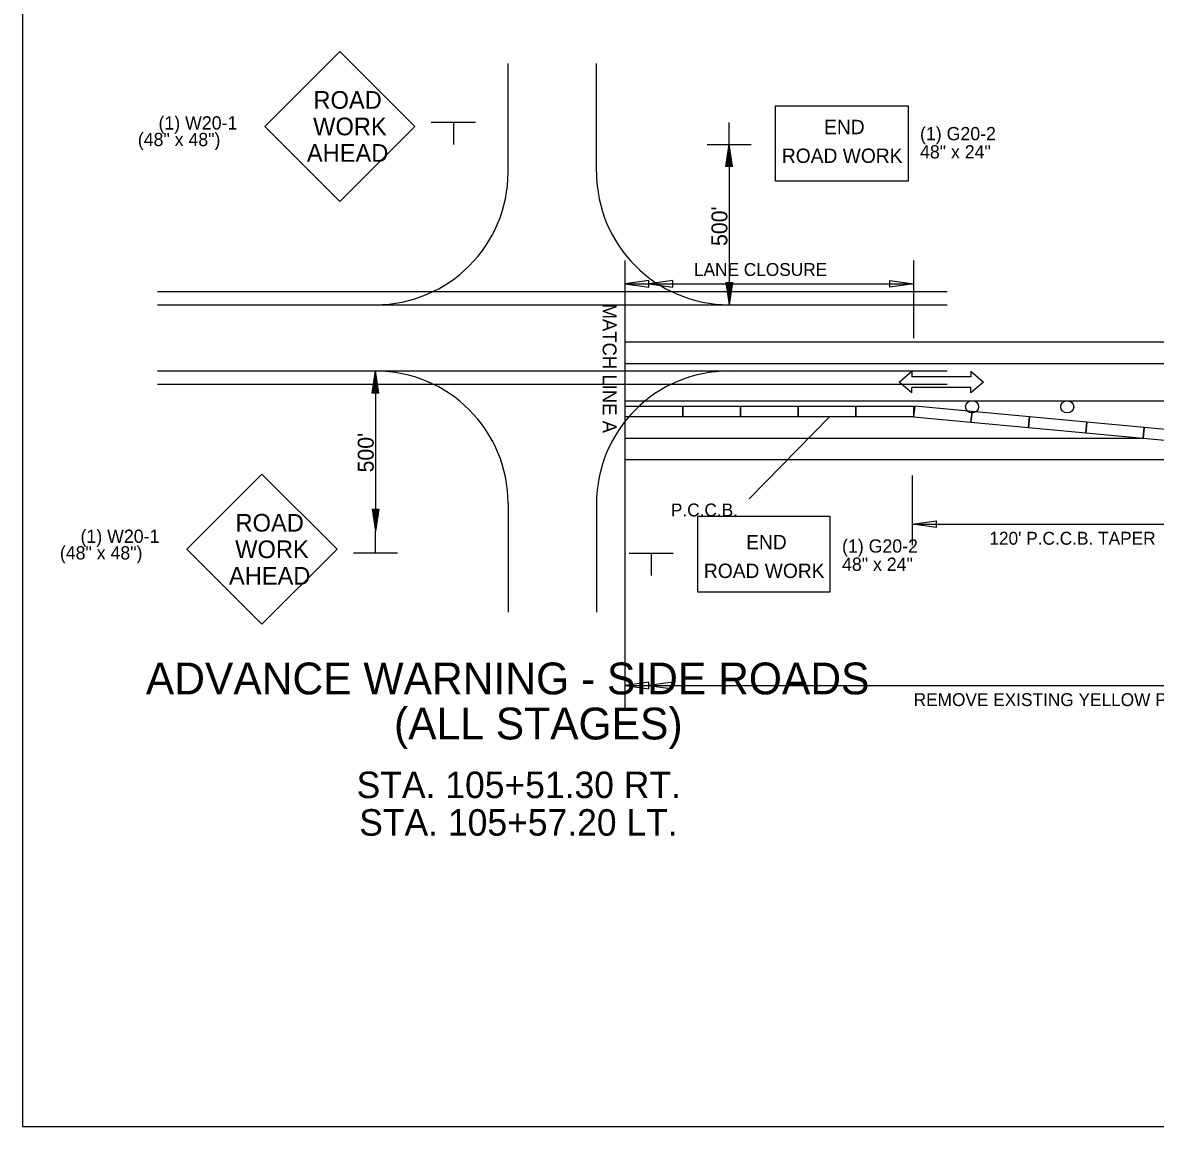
# Model space of a CAD drawing. Extents: x 1807779 to 1818251, y 673292 to 678849.
# Drawn here: x 1810701 to 1811213, y 676380 to 676879 of the extents above; entities that cross this region are included whole.
import ezdxf

# ---------------------------------------------------------------- set-up
doc = ezdxf.new("R2010")
doc.units = 0
for name, color, linetype in [('_ALL STAGES SIGNS', 7, 'Continuous'), ('Default', 7, 'Continuous'), ('DSN_DRFT_Guideline-No-Plot', 7, 'Continuous'), ('R_Draft', 7, 'Continuous'), ('R_MOT', 7, 'Continuous'), ('S_PHOTO_CTL_ANNOT', 7, 'Continuous'), ('T_Vehicle Path Rt', 7, 'Continuous')]:
    doc.layers.add(name, color=color, linetype=linetype)

# ---------------------------------------------------------------- blocks, each defined once
blk = doc.blocks.new('ARROW')
at = {"layer": 'R_Draft'}
for p, q in [((-0.2, 0.03), (0, 0)), ((-0.2, 0.03), (-0.2, -0.03)), ((-0.2, 0.025), (-0.0334, 0)), ((-0.2, 0.0199), (-0.0678, 0)), ((-0.2, 0.0149), (-0.1011, 0)), ((-0.2, 0.0097), (-0.135, 0)), ((-0.2, 0.0047), (-0.1684, 0)), ((-0.2, -0.03), (0, 0)), ((-0.2, -0.0098), (-0.135, 0)), ((-0.2, -0.0199), (-0.0678, 0)), ((-0.2, -0.025), (-0.0334, 0)), ((-0.2, -0.0149), (-0.1011, 0)), ((-0.2, -0.0047), (-0.1684, 0))]:
    blk.add_line(p, q, dxfattribs=at)

msp = doc.modelspace()

# ---------------------------------------------------------------- linework, layer by layer
at = {"layer": '_ALL STAGES SIGNS'}
for points in [[(1810844.4, 676866.37), (1810810.46, 676832.43), (1810844.4, 676798.49), (1810878.34, 676832.43)], [(1810809.13, 676607.12), (1810775.19, 676641.06), (1810809.13, 676675), (1810843.07, 676641.06)]]:
    msp.add_lwpolyline(points, close=True, dxfattribs=at)
at = {"layer": 'Default'}
for p, q in [((1810905.74, 676834.23), (1810885.74, 676834.23)), ((1810895.74, 676834.23), (1810895.74, 676824.23)), ((1811020.47, 676824.23), (1811020.47, 676834.23)), ((1811010.47, 676824.23), (1811030.47, 676824.23)), ((1811020.47, 676824.23), (1811020.47, 676751.75)), ((1810973.46, 676568.94), (1810973.46, 676771.74)), ((1811103.92, 676771.74), (1811103.92, 676736.57)), ((1810984.21, 676762.76), (1810973.46, 676761.25)), ((1810984.21, 676759.75), (1810984.21, 676762.76)), ((1810994.96, 676762.76), (1810984.21, 676761.25)), ((1810994.96, 676759.75), (1810994.96, 676762.76)), ((1811093.17, 676759.75), (1811093.17, 676762.76)), ((1811093.17, 676762.76), (1811103.92, 676761.25)), ((1810973.46, 676761.25), (1811103.92, 676761.25)), ((1810973.46, 676761.25), (1810984.21, 676759.75)), ((1810984.21, 676761.25), (1810994.96, 676759.75)), ((1811103.92, 676761.25), (1811093.17, 676759.75)), ((1810973.46, 676734.92), (1811130.01, 676734.92)), ((1811130.01, 676734.92), (1812078.25, 676734.92)), ((1810860.47, 676721.75), (1810860.47, 676649.26)), ((1810973.46, 676725.19), (1811130.01, 676725.19)), ((1811130.01, 676725.19), (1811412.11, 676725.19)), ((1810973.46, 676708.29), (1811517.44, 676708.29)), ((1811029.52, 676663.93), (1811065.87, 676700.99)), ((1810973.46, 676691.38), (1811130.01, 676691.38)), ((1811130.01, 676691.38), (1811207.5, 676691.38)), ((1810973.46, 676681.65), (1811130.01, 676681.65)), ((1811130.01, 676681.65), (1812078.25, 676681.65)), ((1811103.4, 676642.96), (1811103.4, 676674.42)), ((1811103.4, 676652.48), (1811114.15, 676653.98)), ((1811103.4, 676652.48), (1811259.55, 676652.48)), ((1811114.15, 676650.98), (1811103.4, 676652.48)), ((1811114.15, 676653.98), (1811114.15, 676650.98)), ((1810860.47, 676639.26), (1810860.47, 676649.26)), ((1810870.47, 676639.26), (1810850.47, 676639.26)), ((1810975.19, 676639.26), (1810995.19, 676639.26)), ((1810985.19, 676639.26), (1810985.19, 676629.26)), ((1810984.21, 676580.94), (1810973.46, 676579.43)), ((1810973.46, 676579.43), (1811519.69, 676579.43)), ((1810973.46, 676579.43), (1810984.21, 676577.93)), ((1810984.21, 676577.93), (1810984.21, 676580.94)), ((1810994.96, 676580.94), (1810984.21, 676579.43)), ((1810984.21, 676579.43), (1810994.96, 676577.93)), ((1810994.96, 676577.93), (1810994.96, 676580.94))]:
    msp.add_line(p, q, dxfattribs=at)
for points in [[(1811101.46, 676841.71), (1811101.46, 676807.63), (1811041.47, 676807.63), (1811041.47, 676841.71)], [(1811066.19, 676621.79), (1811066.19, 676655.87), (1811006.2, 676655.87), (1811006.2, 676621.79)]]:
    msp.add_lwpolyline(points, close=True, dxfattribs=at)
msp.add_lwpolyline([(1810973.46, 676708.29), (1811259.55, 676708.29)], dxfattribs=at)
for centre in [(1811130.4, 676705.55), (1811173.45, 676705.55)]:
    msp.add_ellipse(centre, major_axis=(-2.94, 0), ratio=0.93178, dxfattribs=at)
at = {"layer": 'DSN_DRFT_Guideline-No-Plot'}
msp.add_lwpolyline([(1810700.85, 676379.88), (1812350.85, 676379.88), (1812350.85, 677378.94), (1810700.85, 677378.94)], close=True, dxfattribs=at)
at = {"layer": 'R_MOT'}
for p, q in [((1811097.48, 676716.74), (1811103.21, 676721.6)), ((1811103.21, 676721.6), (1811103.21, 676719.17)), ((1811129.8, 676721.6), (1811135.52, 676716.74)), ((1811129.8, 676721.6), (1811129.8, 676719.17)), ((1811103.21, 676711.88), (1811097.48, 676716.74)), ((1811129.8, 676719.17), (1811103.21, 676719.17)), ((1811135.52, 676716.74), (1811129.8, 676711.88)), ((1811129.8, 676714.31), (1811103.21, 676714.31)), ((1811103.21, 676711.88), (1811103.21, 676714.31)), ((1811129.8, 676711.88), (1811129.8, 676714.31))]:
    msp.add_line(p, q, dxfattribs=at)
at = {"layer": 'S_PHOTO_CTL_ANNOT'}
for p, q in [((1810920.47, 676811.75), (1810920.47, 676860.85)), ((1810960.47, 676811.75), (1810960.47, 676860.85)), ((1810761.85, 676757.75), (1811119.08, 676757.75)), ((1810761.85, 676751.75), (1811119.08, 676751.75)), ((1810761.85, 676721.75), (1811119.08, 676721.75)), ((1810761.85, 676715.75), (1811119.08, 676715.75)), ((1810920.47, 676661.75), (1810920.47, 676612.64)), ((1810960.47, 676661.75), (1810960.47, 676612.64))]:
    msp.add_line(p, q, dxfattribs=at)
for centre, start, end in [((1810860.47, 676811.75), 270, 0), ((1811020.47, 676811.75), 180, 270), ((1810860.47, 676661.75), 360, 90), ((1811020.47, 676661.75), 90, 180)]:
    msp.add_arc(centre, 60, start, end, dxfattribs=at)
at = {"layer": 'T_Vehicle Path Rt'}
for points in [[(1810973.46, 676705.85), (1810999.55, 676705.85), (1810999.55, 676700.99), (1810973.46, 676700.99)], [(1810999.55, 676705.85), (1811025.64, 676705.85), (1811025.64, 676700.99), (1810999.55, 676700.99)], [(1811025.64, 676705.85), (1811051.74, 676705.85), (1811051.74, 676700.99), (1811025.64, 676700.99)], [(1811051.74, 676705.85), (1811077.83, 676705.85), (1811077.83, 676700.99), (1811051.74, 676700.99)], [(1811077.83, 676705.85), (1811103.92, 676705.85), (1811103.92, 676700.99), (1811077.83, 676700.99)], [(1811130.4, 676703.42), (1811104.44, 676705.83), (1811103.92, 676700.99), (1811129.89, 676698.58)], [(1811156.37, 676701.01), (1811130.4, 676703.42), (1811129.89, 676698.58), (1811155.85, 676696.17)], [(1811182.33, 676698.6), (1811156.37, 676701.01), (1811155.85, 676696.17), (1811181.81, 676693.76)], [(1811208.3, 676696.19), (1811182.33, 676698.6), (1811181.81, 676693.76), (1811207.78, 676691.35)], [(1811234.26, 676693.78), (1811208.3, 676696.19), (1811207.78, 676691.35), (1811233.74, 676688.94)]]:
    msp.add_lwpolyline(points, close=True, dxfattribs=at)

# ---------------------------------------------------------------- block references
at = {"layer": 'Default', "xscale": 50, "yscale": -50}
for p, rotation in [((1811020.47, 676824.23), 90), ((1811020.47, 676751.75), -90), ((1810860.47, 676721.75), 90), ((1810860.47, 676649.26), -90)]:
    msp.add_blockref('ARROW', p, dxfattribs=dict(at, rotation=rotation))

# ---------------------------------------------------------------- texts
at = {"layer": '_ALL STAGES SIGNS'}
for s, height, p in [('ROAD', 8, (1810832.42, 676840.43)), ('(1) W20-1', 6, (1810762.32, 676831.04)), ('WORK', 8, (1810832.28, 676828.43)), ('(48" x 48")', 6, (1810752.96, 676823.53)), ('AHEAD', 8, (1810829.44, 676816.43))]:
    msp.add_text(s, height=height, rotation=360, dxfattribs=at).set_placement(p)
for s, height, p in [('ROAD', 8, (1810797.15, 676649.06)), ('(1) W20-1', 6, (1810727.04, 676643.97)), ('WORK', 8, (1810797.01, 676637.06)), ('(48" x 48")', 6, (1810717.69, 676636.46)), ('AHEAD', 8, (1810794.17, 676625.06))]:
    msp.add_text(s, height=height, dxfattribs=at).set_placement(p)
at = {"layer": 'Default'}
for s, height, rotation, p in [('END', 6.5, 360, (1811063.45, 676828.93)), ('(1) G20-2', 6, 360, (1811106.84, 676826.19)), ('ROAD WORK', 6.5, 360, (1811044.34, 676815.93)), ('48" x 24"', 6, 360, (1811106.84, 676817.94)), ("500'", 7.2, 90, (1811019.67, 676778.33)), ('MATCH LINE A', 6.2623, 270, (1810963.27, 676752.3)), ("500'", 7.2, 90, (1810859.67, 676675.84))]:
    msp.add_text(s, height=height, rotation=rotation, dxfattribs=at).set_placement(p)
for s, height, p in [('LANE CLOSURE', 5.835, (1811004.57, 676764.76)), ('P.C.C.B.', 5.835, (1810994.14, 676655.94)), ('END', 6.5, (1811028.18, 676641.06)), ('(1) G20-2', 6, (1811071.57, 676639.55)), ("120' P.C.C.B. TAPER", 5.835, (1811138.21, 676643.13)), ('ROAD WORK', 6.5, (1811009.07, 676628.06)), ('48" x 24"', 6, (1811071.57, 676631.3)), ('ADVANCE WARNING - SIDE ROADS', 14.4, (1810756.58, 676575.39)), ('REMOVE EXISTING YELLOW PAVEMENT MARKINGS ALONG C.L.', 5.835, (1811103.97, 676570.09)), ('(ALL STAGES)', 14.4, (1810868.88, 676554.99)), ('STA. 105+51.30 RT.', 12, (1810851.94, 676528.44)), ('STA. 105+57.20 LT.', 12, (1810853.13, 676511.44))]:
    msp.add_text(s, height=height, dxfattribs=at).set_placement(p)

doc.saveas('drawing.dxf')
